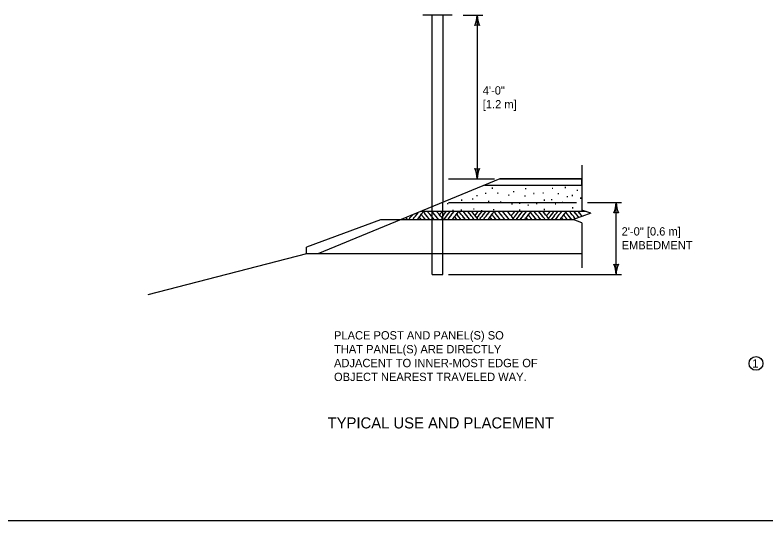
# Model space of a CAD drawing. Extents: x 49991.4 to 50021, y 49987.6 to 50011.4.
# Drawn here: x 50004.88 to 50010.3, y 49987.8 to 49991.45 of the extents above; entities that cross this region are included whole.
import ezdxf

# ---------------------------------------------------------------- set-up
doc = ezdxf.new("R2010")
doc.units = 0
for name, color, linetype in [('Level 1', 7, 'Continuous'), ('Level 2', 7, 'Continuous'), ('Level 3', 7, 'Continuous'), ('Level 4', 7, 'Continuous'), ('Level 6', 7, 'Continuous')]:
    doc.layers.add(name, color=color, linetype=linetype)

msp = doc.modelspace()

# ---------------------------------------------------------------- linework, layer by layer
at = {"layer": 'Level 1'}
for p, q in [((50008.0382, 49991.4539), (50007.8257, 49991.4539)), ((50007.8935, 49990.0683), (50007.8935, 49991.4539)), ((50007.97, 49991.4539), (50007.97, 49990.0998)), ((50008.3822, 49990.2697), (50007.067, 49989.7277)), ((50008.3822, 49990.2697), (50008.2723, 49990.2244)), ((50008.3822, 49990.2697), (50008.9751, 49990.2697)), ((50008.9751, 49990.2697), (50008.3822, 49990.2697)), ((50008.9751, 49990.2243), (50008.9751, 49990.2697)), ((50008.2723, 49990.2244), (50008.9751, 49990.2243)), ((50009.0047, 49990.0336), (50007.8093, 49990.0336)), ((50007.5199, 49989.9751), (50006.9854, 49989.7758)), ((50008.9136, 49989.9751), (50007.5199, 49989.9751)), ((50007.7408, 49989.9986), (50007.7524, 49990.0102)), ((50006.9854, 49989.7277), (50006.9854, 49989.7758)), ((50006.9854, 49989.7277), (50005.8401, 49989.4314)), ((50008.9751, 49989.7277), (50006.9854, 49989.7277))]:
    msp.add_line(p, q, dxfattribs=at)
msp.add_lwpolyline([(49999.3835, 49998.9992), (50016.7501, 49998.9992), (50016.7501, 49987.7988), (49999.3835, 49987.7988)], close=True, dxfattribs=at)
for points in [[(50007.8296, 49990.0336), (50007.8239, 49990.0268), (50007.8247, 49990.0251), (50007.8231, 49990.0251), (50007.8144, 49990.0141), (50007.8121, 49990.0141), (50007.8124, 49990.012), (50007.8035, 49990.0008), (50007.8035, 49989.9987), (50007.8015, 49989.998), (50007.793, 49989.9869), (50007.7909, 49989.9868), (50007.7913, 49989.9847), (50007.7835, 49989.9751)], [(50007.8764, 49989.9751), (50007.8692, 49989.9846), (50007.8674, 49989.9841), (50007.8678, 49989.9858), (50007.859, 49989.9967), (50007.8595, 49989.9989), (50007.8574, 49989.9991), (50007.8485, 49990.0103), (50007.8465, 49990.0108), (50007.8462, 49990.0129), (50007.8374, 49990.0237), (50007.8377, 49990.0258), (50007.8356, 49990.0258), (50007.8295, 49990.0336)], [(50007.9082, 49989.9751), (50007.8996, 49989.9864), (50007.8978, 49989.986), (50007.8981, 49989.9876), (50007.8893, 49989.9985), (50007.8898, 49990.0007), (50007.8877, 49990.0009), (50007.8789, 49990.0122), (50007.8768, 49990.0126), (50007.8766, 49990.0147), (50007.8677, 49990.0255), (50007.8681, 49990.0276), (50007.8659, 49990.0277), (50007.8613, 49990.0336)], [(50007.9406, 49989.9751), (50007.9326, 49989.9855), (50007.9308, 49989.9851), (50007.9312, 49989.9867), (50007.9223, 49989.9977), (50007.9229, 49989.9999), (50007.9207, 49990.0001), (50007.9119, 49990.0113), (50007.9098, 49990.0118), (50007.9096, 49990.0139), (50007.9008, 49990.0247), (50007.9011, 49990.0268), (50007.8989, 49990.0268), (50007.8937, 49990.0336)], [(50007.9509, 49990.0044), (50007.9426, 49990.015), (50007.9406, 49990.0154), (50007.9403, 49990.0175), (50007.9315, 49990.0283), (50007.9319, 49990.0304), (50007.9297, 49990.0304), (50007.9273, 49990.0336)], [(50007.9653, 49990.0336), (50007.9616, 49990.0292), (50007.9624, 49990.0275), (50007.9607, 49990.0275), (50007.9521, 49990.0165), (50007.9509, 49990.0165)], [(50007.9928, 49990.0336), (50007.9805, 49990.0177), (50007.9782, 49990.0177), (50007.9785, 49990.0156), (50007.9695, 49990.0044), (50007.9695, 49990.0023), (50007.9676, 49990.0016), (50007.9604, 49989.9923)], [(50008.0207, 49990.0336), (50008.0069, 49990.0162), (50008.0046, 49990.0162), (50008.0049, 49990.0141), (50007.996, 49990.0029), (50007.996, 49990.0008), (50007.994, 49990.0001), (50007.9747, 49989.9751)], [(50008.0492, 49990.0336), (50008.0357, 49990.0165), (50008.0335, 49990.0165), (50008.0338, 49990.0144), (50008.0248, 49990.0032), (50008.0248, 49990.0011), (50008.0229, 49990.0004), (50008.0143, 49989.9893), (50008.0122, 49989.9892), (50008.0126, 49989.9871), (50008.003, 49989.9751)], [(50008.0823, 49990.0336), (50008.0696, 49990.0176), (50008.0673, 49990.0176), (50008.0676, 49990.0155), (50008.0587, 49990.0043), (50008.0587, 49990.0022), (50008.0567, 49990.0015), (50008.0482, 49989.9904), (50008.0461, 49989.9903), (50008.0465, 49989.9882), (50008.0357, 49989.9751)], [(50008.1344, 49989.9751), (50008.1244, 49989.9881), (50008.1226, 49989.9876), (50008.123, 49989.9893), (50008.1142, 49990.0002), (50008.1147, 49990.0024), (50008.1126, 49990.0026), (50008.1037, 49990.0138), (50008.1017, 49990.0143), (50008.1014, 49990.0164), (50008.0874, 49990.0336)], [(50008.1661, 49989.9751), (50008.1548, 49989.9899), (50008.153, 49989.9895), (50008.1533, 49989.9911), (50008.1445, 49990.002), (50008.145, 49990.0042), (50008.1429, 49990.0044), (50008.1341, 49990.0157), (50008.132, 49990.0161), (50008.1318, 49990.0182), (50008.1191, 49990.0336)], [(50008.1984, 49989.9751), (50008.1878, 49989.9891), (50008.186, 49989.9886), (50008.1864, 49989.9903), (50008.1775, 49990.0012), (50008.1781, 49990.0034), (50008.1759, 49990.0036), (50008.1671, 49990.0148), (50008.165, 49990.0153), (50008.1648, 49990.0174), (50008.1516, 49990.0336)], [(50008.2061, 49990.0009), (50008.1978, 49990.0115), (50008.1958, 49990.0119), (50008.1955, 49990.014), (50008.1796, 49990.0336)], [(50008.2234, 49990.0336), (50008.2168, 49990.0257), (50008.2176, 49990.024), (50008.2159, 49990.024), (50008.2073, 49990.013), (50008.2061, 49990.013)], [(50008.2507, 49990.0336), (50008.2357, 49990.0142), (50008.2334, 49990.0142), (50008.2337, 49990.0121), (50008.2247, 49990.0009), (50008.2247, 49989.9988), (50008.2228, 49989.9981), (50008.2156, 49989.9888)], [(50008.2784, 49990.0336), (50008.2716, 49990.0254), (50008.2724, 49990.0237), (50008.2708, 49990.0237), (50008.2621, 49990.0127), (50008.2598, 49990.0127), (50008.2601, 49990.0106), (50008.2512, 49989.9994), (50008.2512, 49989.9973), (50008.2492, 49989.9966), (50008.2407, 49989.9855), (50008.2386, 49989.9854), (50008.239, 49989.9833), (50008.2322, 49989.9751)], [(50008.307, 49990.0336), (50008.3004, 49990.0257), (50008.3013, 49990.024), (50008.2996, 49990.024), (50008.2909, 49990.013), (50008.2887, 49990.013), (50008.289, 49990.0109), (50008.28, 49989.9997), (50008.28, 49989.9976), (50008.2781, 49989.9969), (50008.2695, 49989.9858), (50008.2674, 49989.9857), (50008.2678, 49989.9836), (50008.261, 49989.9751)], [(50008.34, 49990.0336), (50008.3343, 49990.0268), (50008.3351, 49990.0251), (50008.3335, 49990.0251), (50008.3248, 49990.0141), (50008.3225, 49990.0141), (50008.3228, 49990.012), (50008.3139, 49990.0008), (50008.3139, 49989.9987), (50008.3119, 49989.998), (50008.3034, 49989.9869), (50008.3013, 49989.9868), (50008.3017, 49989.9847), (50008.2939, 49989.9751)], [(50008.3868, 49989.9751), (50008.3796, 49989.9846), (50008.3778, 49989.9841), (50008.3782, 49989.9858), (50008.3694, 49989.9967), (50008.3699, 49989.9989), (50008.3678, 49989.9991), (50008.3589, 49990.0103), (50008.3569, 49990.0108), (50008.3566, 49990.0129), (50008.3478, 49990.0237), (50008.3481, 49990.0258), (50008.346, 49990.0258), (50008.3399, 49990.0336)], [(50008.4186, 49989.9751), (50008.41, 49989.9864), (50008.4082, 49989.986), (50008.4085, 49989.9876), (50008.3997, 49989.9985), (50008.4002, 49990.0007), (50008.3981, 49990.0009), (50008.3893, 49990.0122), (50008.3872, 49990.0126), (50008.387, 49990.0147), (50008.3714, 49990.0336)], [(50008.451, 49989.9751), (50008.443, 49989.9855), (50008.4412, 49989.9851), (50008.4416, 49989.9867), (50008.4327, 49989.9977), (50008.4333, 49989.9999), (50008.4311, 49990.0001), (50008.4223, 49990.0113), (50008.4202, 49990.0118), (50008.42, 49990.0139), (50008.4112, 49990.0247), (50008.4115, 49990.0268), (50008.4093, 49990.0268), (50008.4041, 49990.0336)], [(50008.4682, 49989.9975), (50008.4599, 49990.0081), (50008.4579, 49990.0085), (50008.4576, 49990.0106), (50008.4388, 49990.0336)], [(50008.4883, 49990.0336), (50008.4789, 49990.0223), (50008.4797, 49990.0206), (50008.478, 49990.0206), (50008.4694, 49990.0096), (50008.4682, 49990.0096)], [(50008.5155, 49990.0336), (50008.4978, 49990.0108), (50008.4955, 49990.0108), (50008.4958, 49990.0087), (50008.4868, 49989.9975), (50008.4868, 49989.9954), (50008.4849, 49989.9947), (50008.4777, 49989.9854)], [(50008.5434, 49990.0336), (50008.5242, 49990.0093), (50008.5219, 49990.0093), (50008.5222, 49990.0072), (50008.5133, 49989.996), (50008.5133, 49989.9939), (50008.5113, 49989.9932), (50008.5028, 49989.9821), (50008.5007, 49989.982), (50008.5011, 49989.9799), (50008.4971, 49989.9751)], [(50008.572, 49990.0336), (50008.553, 49990.0096), (50008.5508, 49990.0096), (50008.5511, 49990.0075), (50008.5421, 49989.9963), (50008.5421, 49989.9942), (50008.5402, 49989.9935), (50008.5316, 49989.9824), (50008.5295, 49989.9823), (50008.5299, 49989.9802), (50008.5258, 49989.9751)], [(50008.6048, 49990.0336), (50008.5869, 49990.0107), (50008.5846, 49990.0107), (50008.5849, 49990.0086), (50008.576, 49989.9974), (50008.576, 49989.9953), (50008.574, 49989.9946), (50008.5655, 49989.9835), (50008.5634, 49989.9834), (50008.5638, 49989.9813), (50008.5587, 49989.9751)], [(50008.6463, 49989.9751), (50008.6417, 49989.9812), (50008.6399, 49989.9807), (50008.6403, 49989.9824), (50008.6315, 49989.9933), (50008.632, 49989.9955), (50008.6299, 49989.9957), (50008.621, 49990.0069), (50008.619, 49990.0074), (50008.6187, 49990.0095), (50008.6099, 49990.0203), (50008.6102, 49990.0224), (50008.6081, 49990.0224), (50008.6021, 49990.0301)], [(50008.6781, 49989.9751), (50008.6721, 49989.983), (50008.6703, 49989.9826), (50008.6706, 49989.9842), (50008.6618, 49989.9951), (50008.6623, 49989.9973), (50008.6602, 49989.9975), (50008.6514, 49990.0088), (50008.6493, 49990.0092), (50008.6491, 49990.0113), (50008.6309, 49990.0336)], [(50008.7105, 49989.9751), (50008.7051, 49989.9821), (50008.7033, 49989.9817), (50008.7037, 49989.9833), (50008.6949, 49989.9943), (50008.6954, 49989.9965), (50008.6932, 49989.9967), (50008.6844, 49990.0079), (50008.6823, 49990.0084), (50008.6821, 49990.0105), (50008.6733, 49990.0213), (50008.6736, 49990.0234), (50008.6714, 49990.0234), (50008.6636, 49990.0336)], [(50008.7234, 49989.9975), (50008.7151, 49990.0081), (50008.7131, 49990.0085), (50008.7129, 49990.0106), (50008.704, 49990.0214), (50008.7044, 49990.0235), (50008.7022, 49990.0235), (50008.6945, 49990.0336)], [(50008.7434, 49990.0336), (50008.734, 49990.0223), (50008.7348, 49990.0206), (50008.7331, 49990.0206), (50008.7245, 49990.0096), (50008.7233, 49990.0096)], [(50008.7707, 49990.0336), (50008.7624, 49990.0235), (50008.7632, 49990.0219), (50008.7615, 49990.0219), (50008.7529, 49990.0108), (50008.7506, 49990.0108), (50008.7509, 49990.0087), (50008.7419, 49989.9975), (50008.7419, 49989.9954), (50008.74, 49989.9947), (50008.7328, 49989.9854)], [(50008.7985, 49990.0336), (50008.7888, 49990.022), (50008.7896, 49990.0203), (50008.788, 49990.0203), (50008.7793, 49990.0093), (50008.777, 49990.0093), (50008.7773, 49990.0072), (50008.7684, 49989.996), (50008.7684, 49989.9939), (50008.7664, 49989.9932), (50008.7579, 49989.9821), (50008.7558, 49989.982), (50008.7562, 49989.9799), (50008.7522, 49989.9751)], [(50008.827, 49990.0336), (50008.8176, 49990.0223), (50008.8185, 49990.0206), (50008.8168, 49990.0206), (50008.8081, 49990.0096), (50008.8059, 49990.0096), (50008.8062, 49990.0075), (50008.7972, 49989.9963), (50008.7972, 49989.9942), (50008.7953, 49989.9935), (50008.7867, 49989.9824), (50008.7846, 49989.9823), (50008.785, 49989.9802), (50008.7809, 49989.9751)], [(50008.86, 49990.0336), (50008.8515, 49990.0234), (50008.8523, 49990.0217), (50008.8507, 49990.0217), (50008.842, 49990.0107), (50008.8397, 49990.0107), (50008.84, 49990.0086), (50008.8311, 49989.9974), (50008.8311, 49989.9953), (50008.8291, 49989.9946), (50008.8206, 49989.9835), (50008.8185, 49989.9834), (50008.8189, 49989.9813), (50008.8138, 49989.9751)], [(50008.9014, 49989.9751), (50008.8968, 49989.9812), (50008.895, 49989.9807), (50008.8954, 49989.9824), (50008.8866, 49989.9933), (50008.8871, 49989.9955), (50008.885, 49989.9957), (50008.8761, 49990.0069), (50008.8741, 49990.0074), (50008.8738, 49990.0095), (50008.865, 49990.0203), (50008.8653, 49990.0224), (50008.8632, 49990.0224), (50008.8571, 49990.0302)], [(50008.9276, 49989.9818), (50008.9169, 49989.9951), (50008.9174, 49989.9973), (50008.9153, 49989.9975), (50008.9065, 49990.0088), (50008.9044, 49990.0092), (50008.9042, 49990.0113), (50008.8953, 49990.0221), (50008.8957, 49990.0242), (50008.8935, 49990.0243), (50008.8863, 49990.0336)], [(50008.9529, 49989.9908), (50008.9395, 49990.0079), (50008.9374, 49990.0084), (50008.9372, 49990.0105), (50008.9284, 49990.0213), (50008.9287, 49990.0234), (50008.9265, 49990.0234), (50008.9187, 49990.0336)], [(50008.9771, 49989.9994), (50008.9591, 49990.0214), (50008.9595, 49990.0235), (50008.9573, 49990.0235), (50008.9496, 49990.0336)], [(50007.7162, 49989.9751), (50007.7081, 49989.9857), (50007.7063, 49989.9853), (50007.7067, 49989.9869), (50007.704, 49989.9902)], [(50007.7408, 49989.9986), (50007.7408, 49989.9973), (50007.7388, 49989.9966), (50007.7303, 49989.9855), (50007.7282, 49989.9854), (50007.7286, 49989.9833), (50007.7218, 49989.9751)], [(50007.7906, 49990.0259), (50007.7696, 49989.9997), (50007.7696, 49989.9976), (50007.7677, 49989.9969), (50007.7591, 49989.9858), (50007.757, 49989.9857), (50007.7574, 49989.9836), (50007.7506, 49989.9751)], [(50007.8156, 49989.9751), (50007.8073, 49989.9854), (50007.8076, 49989.9874), (50007.8055, 49989.9875), (50007.7994, 49989.9953)], [(50007.8457, 49989.9751), (50007.8331, 49989.9909), (50007.8311, 49989.9914), (50007.8308, 49989.9934), (50007.822, 49990.0042), (50007.8223, 49990.0063), (50007.8202, 49990.0064), (50007.8142, 49990.0141)], [(50007.9509, 49990.0165), (50007.9498, 49990.0165), (50007.9501, 49990.0144), (50007.9466, 49990.0099)], [(50007.974, 49989.9751), (50007.9633, 49989.9892), (50007.9615, 49989.9887), (50007.9619, 49989.9904), (50007.9531, 49990.0013), (50007.9536, 49990.0035), (50007.9515, 49990.0037), (50007.9509, 49990.0044)], [(50008.0736, 49989.9751), (50008.0625, 49989.9889), (50008.0628, 49989.9909), (50008.0607, 49989.991), (50008.0546, 49989.9988)], [(50008.1036, 49989.9751), (50008.0883, 49989.9944), (50008.0863, 49989.9949), (50008.086, 49989.9969), (50008.0772, 49990.0077), (50008.0775, 49990.0098), (50008.0754, 49990.0099), (50008.0694, 49990.0176)], [(50008.2061, 49990.013), (50008.205, 49990.013), (50008.2053, 49990.0109), (50008.2018, 49990.0064)], [(50008.2266, 49989.9751), (50008.2185, 49989.9857), (50008.2167, 49989.9853), (50008.2171, 49989.9869), (50008.2083, 49989.9978), (50008.2088, 49990), (50008.2067, 49990.0002), (50008.2061, 49990.0009)], [(50008.326, 49989.9751), (50008.3177, 49989.9854), (50008.318, 49989.9874), (50008.3159, 49989.9875), (50008.3098, 49989.9953)], [(50008.3561, 49989.9751), (50008.3435, 49989.9909), (50008.3415, 49989.9914), (50008.3412, 49989.9934), (50008.3324, 49990.0042), (50008.3327, 49990.0063), (50008.3306, 49990.0064), (50008.3246, 49990.0141)], [(50008.4682, 49990.0096), (50008.4671, 49990.0096), (50008.4674, 49990.0075), (50008.4639, 49990.003)], [(50008.4861, 49989.9751), (50008.4806, 49989.9823), (50008.4788, 49989.9819), (50008.4792, 49989.9835), (50008.4704, 49989.9944), (50008.4709, 49989.9966), (50008.4688, 49989.9968), (50008.4682, 49989.9975)], [(50008.5854, 49989.9751), (50008.5798, 49989.982), (50008.5801, 49989.984), (50008.578, 49989.9841), (50008.5719, 49989.9919)], [(50008.6155, 49989.9751), (50008.6056, 49989.9875), (50008.6036, 49989.988), (50008.6033, 49989.99), (50008.5945, 49990.0008), (50008.5948, 49990.0029), (50008.5927, 49990.003), (50008.5867, 49990.0107)], [(50008.7234, 49990.0096), (50008.7223, 49990.0096), (50008.7226, 49990.0075), (50008.7191, 49990.003)], [(50008.7412, 49989.9751), (50008.7357, 49989.9823), (50008.7339, 49989.9819), (50008.7343, 49989.9835), (50008.7255, 49989.9944), (50008.726, 49989.9966), (50008.7239, 49989.9968), (50008.7233, 49989.9975)], [(50008.8405, 49989.9751), (50008.8349, 49989.982), (50008.8352, 49989.984), (50008.8331, 49989.9841), (50008.827, 49989.9919)], [(50008.8706, 49989.9751), (50008.8607, 49989.9875), (50008.8587, 49989.988), (50008.8584, 49989.99), (50008.8496, 49990.0008), (50008.8499, 49990.0029), (50008.8478, 49990.003), (50008.8418, 49990.0107)]]:
    msp.add_lwpolyline(points, dxfattribs=at)
at = {"layer": 'Level 2'}
msp.add_circle((50010.2321, 49988.9373), 0.05, dxfattribs=at)
at = {"layer": 'Level 3'}
for p, q in [((50008.1182, 49991.4539), (50008.2585, 49991.4539)), ((50008.2185, 49991.4539), (50008.2185, 49990.2697)), ((50008.01, 49990.2697), (50008.3422, 49990.2697)), ((50008.01, 49990.0998), (50008.9351, 49990.0998)), ((50009.0151, 49990.0998), (50009.2616, 49990.0998)), ((50009.2216, 49989.5787), (50009.2216, 49990.0998)), ((50008.01, 49989.5787), (50009.2616, 49989.5787))]:
    msp.add_line(p, q, dxfattribs=at)
for centre, radius, start, end in [((50007.9964, 49991.4631), 0.2223, 337.456, 357.6395), ((50008.4512, 49991.4654), 0.233, 182.8273, 202.0772), ((50008.2185, 49991.3257), 0.0548, 72.1388, 107.8612), ((50008.2185, 49990.3979), 0.0548, 252.1388, 287.8612), ((50007.9858, 49990.2582), 0.233, 2.8273, 22.0772), ((50008.4406, 49990.2605), 0.2223, 157.456, 177.6395), ((50008.9995, 49990.109), 0.2223, 337.456, 357.6395), ((50009.4543, 49990.1113), 0.233, 182.8273, 202.0772), ((50009.2216, 49989.9716), 0.0548, 72.1388, 107.8612), ((50009.2216, 49989.7069), 0.0548, 252.1388, 287.8612), ((50008.9889, 49989.5672), 0.233, 2.8273, 22.0772), ((50009.4437, 49989.5695), 0.2223, 157.456, 177.6395)]:
    msp.add_arc(centre, radius, start, end, dxfattribs=at)
at = {"layer": 'Level 4'}
for p, q in [((50007.97, 49989.5787), (50007.97, 49990.0998)), ((50007.8935, 49989.5787), (50007.8935, 49990.0683)), ((50007.8935, 49989.5787), (50007.97, 49989.5787))]:
    msp.add_line(p, q, dxfattribs=at)
at = {"layer": 'Level 6'}
for p, q in [((50008.9751, 49990.3697), (50008.9751, 49990.0441)), ((50009.0391, 49990.0214), (50008.9751, 49990.0441)), ((50008.9751, 49989.9987), (50008.9111, 49989.976)), ((50008.9751, 49989.9533), (50008.9111, 49989.976)), ((50009.0391, 49990.0214), (50008.9751, 49989.9987)), ((50008.9751, 49989.9533), (50008.9751, 49989.6277))]:
    msp.add_line(p, q, dxfattribs=at)

# ---------------------------------------------------------------- texts
at = {"layer": 'Level 1'}
for p in [(50008.3155, 49990.1973), (50008.555, 49990.1936), (50008.7495, 49990.1961), (50008.8418, 49990.2023), (50008.9291, 49990.1824), (50008.2045, 49990.1437), (50008.2669, 49990.1599), (50008.3542, 49990.1612), (50008.434, 49990.1474), (50008.4689, 49990.1724), (50008.5512, 49990.1412), (50008.6148, 49990.1587), (50008.6822, 49990.1624), (50008.7919, 49990.1574), (50008.8568, 49990.1362), (50008.8917, 49990.1449), (50008.9531, 49990.1249), (50007.9925, 49990.0851), (50008.0936, 49990.1113), (50008.1721, 49990.1188), (50008.2884, 49990.1025), (50008.3744, 49990.0975), (50008.4565, 49990.0838), (50008.5116, 49990.0887), (50008.5732, 49990.075), (50008.6348, 49990.0863), (50008.6899, 49990.1112), (50008.7433, 49990.115), (50008.7707, 49990.0838), (50008.8218, 49990.0951), (50008.0312, 49990.0377), (50008.0911, 49990.0402), (50008.1809, 49990.0477), (50008.237, 49990.034), (50008.3243, 49990.0427), (50008.5121, 49990.0403), (50008.6897, 49990.0439), (50008.8954, 49990.0552)]:
    msp.add_text('.', height=0.07, dxfattribs=at).set_placement(p)
at = {"layer": 'Level 2'}
for s, p in [('4\'-0"', (50008.2585, 49990.8793)), ('[1.2 m]', (50008.2585, 49990.7793)), ('2\'-0" [0.6 m]', (50009.2616, 49989.8607)), ('EMBEDMENT', (50009.2616, 49989.7607))]:
    msp.add_text(s, height=0.06, rotation=0.0293, dxfattribs=at).set_placement(p)
for s, height, p in [('PLACE POST AND PANEL(S) SO', 0.06, (50007.1843, 49989.1099)), ('THAT PANEL(S) ARE DIRECTLY', 0.06, (50007.1843, 49989.0099)), ('ADJACENT TO INNER-MOST EDGE OF', 0.06, (50007.1843, 49988.9099)), ('1', 0.06, (50010.2051, 49988.9073)), ('OBJECT NEAREST TRAVELED WAY.', 0.06, (50007.1843, 49988.8099)), ('TYPICAL USE AND PLACEMENT', 0.08, (50007.1381, 49988.4673))]:
    msp.add_text(s, height=height, dxfattribs=at).set_placement(p)

doc.saveas('drawing.dxf')
